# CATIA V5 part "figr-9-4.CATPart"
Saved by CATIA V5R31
Part number: Part1
Bounding box of the stored display mesh (mm): x -71.324 to 69.61, y -139.735 to 0, z 0 to 45
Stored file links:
  D:\PROJECTS\Project 2021\US EDITION\CATIA V5 6R 2021\Resources\Part Files\c09_catia_v5_6r2021_prt\c09_catia_v5_6r2021_prt\figr-9-4.CATPart
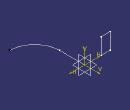
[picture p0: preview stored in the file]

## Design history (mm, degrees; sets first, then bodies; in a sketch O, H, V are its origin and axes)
Body1 (main body)
  Sketch1 on xy-plane, origin (0, 0, 0), H (1, 0, 0), V (0, 1, 0)
    line L1 (0, 0) -> (0, -70.1255)
    arc A1 centre (69.6095, -70.1255) radius 69.6095 from (0, -70.1255) to (69.6095, -139.7351) ccw
    vertical: L1 V
    tangency: A1 L1
  Sketch2 on zx-plane, origin (0, 0, 0), H (-1, 0, 0), V (0, 0, 1)
    point P1 (46.3244, 0)
    line L1 (46.3244, 0) -> (71.3244, 0)
    line L2 (71.3244, 0) -> (71.3244, 45)
    line L3 (71.3244, 45) -> (46.3244, 45)
    line L4 (46.3244, 45) -> (46.3244, 0)
    length L3 = 25
    length L2 = 45
    coincidence: P1 H
    horizontal: L1 H, L3 H
    vertical: L2 V, L4 V
  Rib1: profile Sketch2, centre curve Sketch1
